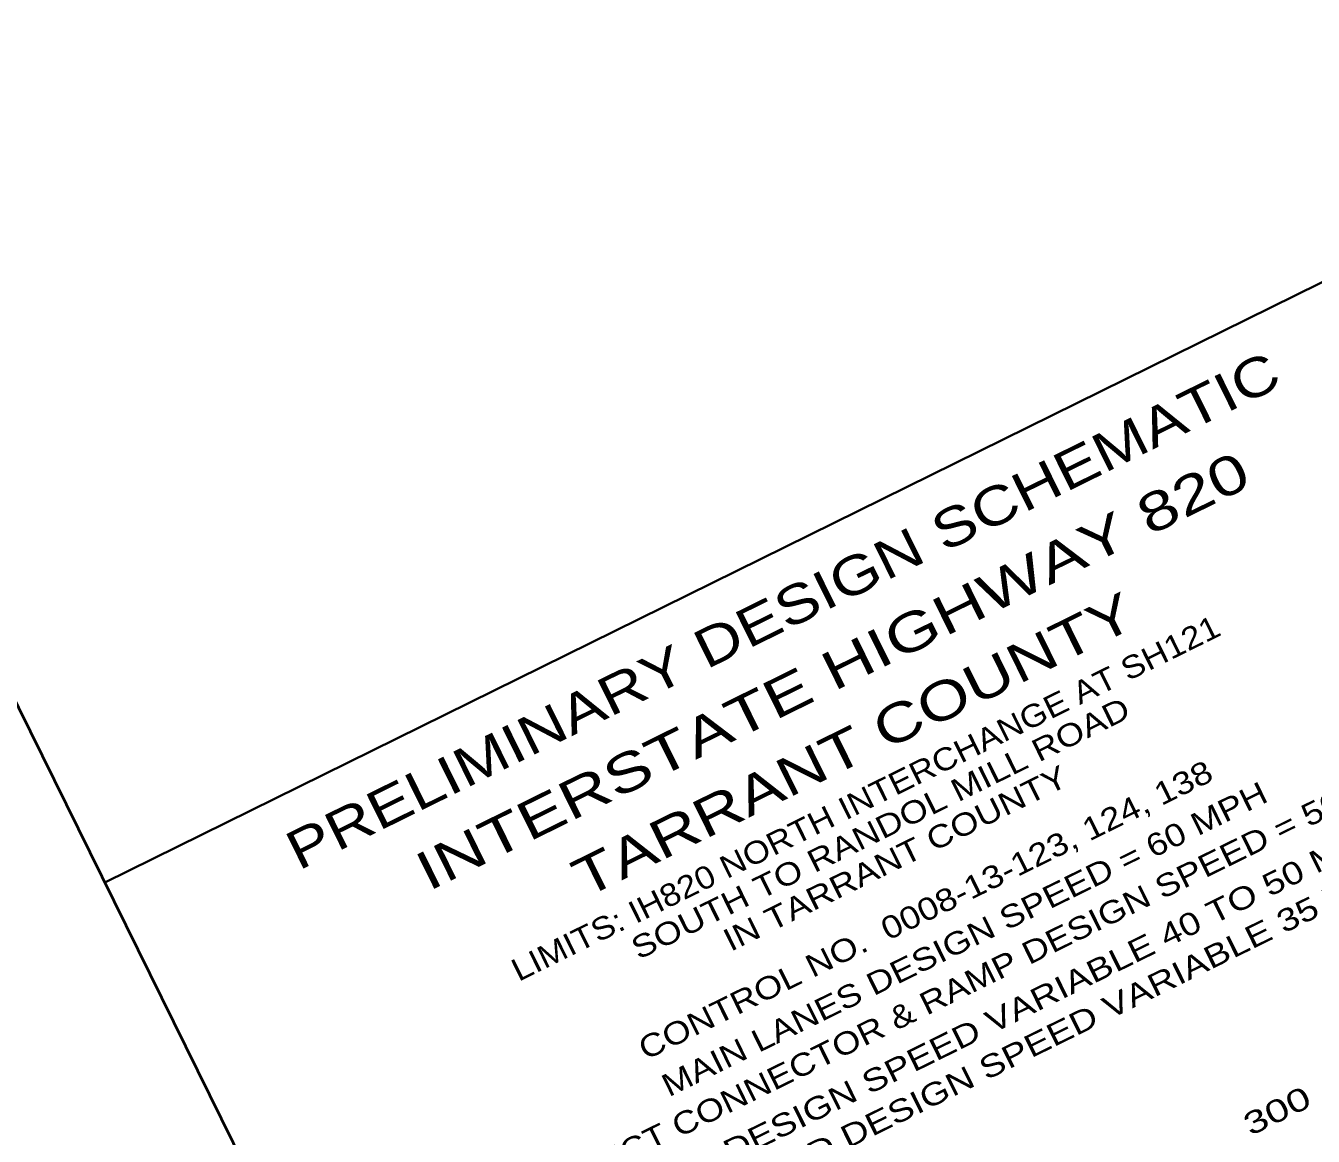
# Model space of a CAD drawing. Extents: x 2356606 to 2371222, y 6973096 to 6982644.
# Drawn here: x 2357945 to 2358529, y 6973650 to 6974155 of the extents above; entities that cross this region are included whole.
import ezdxf
from ezdxf.enums import TextEntityAlignment as Align

# ---------------------------------------------------------------- set-up
doc = ezdxf.new("R2010")
doc.units = 0
doc.header["$LTSCALE"] = 2
for name, color, linetype, lineweight in [('44', 7, 'Continuous', 13), ('62', 7, 'Continuous', 13), ('63', 7, 'Continuous', 13)]:
    doc.layers.add(name, color=color, linetype=linetype, lineweight=lineweight)
doc.layers.add('61', color=7, linetype='Continuous')

msp = doc.modelspace()

# ---------------------------------------------------------------- linework, layer by layer
at = {"layer": '44', "lineweight": 40}
msp.add_lwpolyline([(2358244.847, 6973230.201), (2356740.046, 6976279.238), (2369364.897, 6982510.022)], dxfattribs=at)
at = {"layer": '62', "lineweight": 35}
msp.add_line((2357980.697, 6973765.424), (2358564.491, 6974053.546), dxfattribs=at)

# ---------------------------------------------------------------- texts
at = {"layer": '61'}
for s, width, p in [('LIMITS: IH820 NORTH INTERCHANGE AT SH121', 1.15, (2358328.375, 6973799.162)), ('SOUTH TO RANDOL MILL ROAD', 1.2, (2358335.102, 6973785.532)), ('IN TARRANT COUNTY', 1.2, (2358341.829, 6973771.902))]:
    msp.add_text(s, height=10.2, rotation=26.268, dxfattribs=dict(at, width=width)).set_placement(p, align=Align.CENTER)
at = {"layer": '62'}
for s, height, width, p in [('PRELIMINARY DESIGN SCHEMATIC', 17.5, 1.25, (2358068.696, 6973770.695)), ('INTERSTATE HIGHWAY 820', 17.5, 1.35, (2358127.645, 6973761.272)), ('TARRANT COUNTY', 17.5, 1.3, (2358198.644, 6973758.112)), ('CONTROL NO.  0008-13-123, 124, 138', 10.2, 1.2, (2358226.224, 6973684.576)), ('PRELIMINARY PLAN', 11.74, 1.15, (2358518.728, 6973591.634))]:
    msp.add_text(s, height=height, rotation=26.268, dxfattribs=dict(at, width=width)).set_placement(p)
for s, width, p in [('DIRECT CONNECTOR & RAMP DESIGN SPEED = 50 MPH', 1.2, (2358381.426, 6973718.525)), ('MAIN LANES DESIGN SPEED = 60 MPH', 1.2, (2358373.205, 6973735.185)), ('FRONTAGE ROAD DESIGN SPEED VARIABLE 35 TO 40 MPH', 1.25, (2358399.194, 6973684.505)), ('RAMP DESIGN SPEED VARIABLE 40 TO 50 MPH', 1.25, (2358390.532, 6973700.074)), ('300', 1.4, (2358515.199, 6973657.187))]:
    msp.add_text(s, height=10.2, rotation=26.268, dxfattribs=dict(at, width=width)).set_placement(p, align=Align.CENTER)
at = {"layer": '63'}
for s, width, p in [('DIRECT CONNECTOR & RAMP DESIGN SPEED = 50 MPH', 1.2, (2358381.426, 6973718.525)), ('MAIN LANES DESIGN SPEED = 60 MPH', 1.2, (2358373.205, 6973735.185)), ('300', 1.4, (2358515.199, 6973657.187))]:
    msp.add_text(s, height=10.2, rotation=26.268, dxfattribs=dict(at, width=width)).set_placement(p, align=Align.CENTER)

doc.saveas('drawing.dxf')
